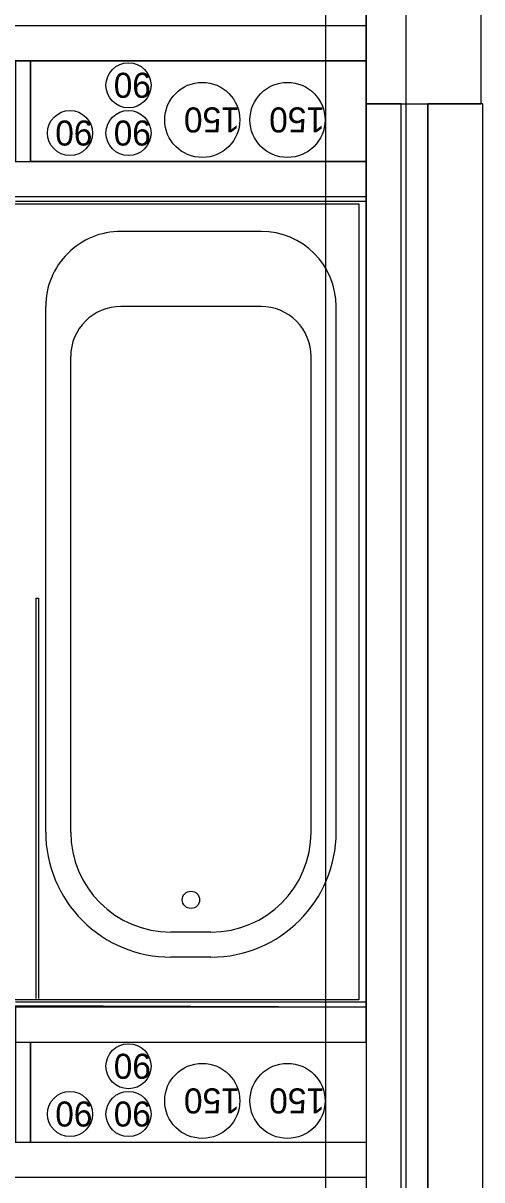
# Model space of a CAD drawing. Extents: x 1278 to 1356, y -253.7 to -224.
# Drawn here: x 1302.645 to 1303.561, y -239.071 to -236.76 of the extents above; entities that cross this region are included whole.
import ezdxf

# ---------------------------------------------------------------- set-up
doc = ezdxf.new("R2010")
doc.units = 0
for name, color, linetype in [('Level 1', 7, 'Continuous'), ('Level 11', 7, 'Continuous'), ('Level 36', 7, 'Continuous'), ('Level 41', 7, 'Continuous'), ('Level 65', 7, 'Continuous'), ('Level 66', 7, 'Continuous'), ('Level 67', 7, 'Continuous'), ('Level 70', 7, 'Continuous'), ('Level 93', 7, 'Continuous')]:
    doc.layers.add(name, color=color, linetype=linetype)

msp = doc.modelspace()

# ---------------------------------------------------------------- linework, layer by layer
at = {"layer": 'Level 1'}
for p, q in [((1301.8535, -236.8352), (1303.3298, -236.8352)), ((1303.3298, -238.7263), (1301.7835, -238.7263)), ((1303.3294, -239.0663), (1301.0027, -239.0663))]:
    msp.add_line(p, q, dxfattribs=at)
at = {"layer": 'Level 11'}
for p, q in [((1303.3298, -237.1163), (1302.6298, -237.1163)), ((1303.3298, -238.7163), (1303.3298, -237.1163)), ((1303.1198, -237.1763), (1302.8398, -237.1763)), ((1302.6898, -238.3763), (1302.6898, -237.3263)), ((1303.1198, -237.3263), (1302.8398, -237.3263)), ((1303.2698, -238.3763), (1303.2698, -237.3263)), ((1302.7398, -238.3763), (1302.7398, -237.4263)), ((1303.2198, -238.3763), (1303.2198, -237.4263)), ((1303.0198, -238.5763), (1302.9398, -238.5763)), ((1303.0198, -238.6263), (1302.9398, -238.6263)), ((1303.3298, -238.7163), (1302.6298, -238.7163))]:
    msp.add_line(p, q, dxfattribs=at)
msp.add_circle((1302.9798, -238.5118), 0.0173, dxfattribs=at)
for centre, radius, start, end in [((1302.8398, -237.3263), 0.15, 89.9999, 180.0002), ((1303.1198, -237.3263), 0.15, 360, 90), ((1302.8398, -237.4263), 0.1, 90.0001, 179.9999), ((1303.1198, -237.4263), 0.1, 360, 90.0001), ((1302.9398, -238.3763), 0.25, 180, 270.0001), ((1302.9398, -238.3763), 0.2, 180, 270), ((1303.0198, -238.3763), 0.25, 269.9999, 359.9999), ((1303.0198, -238.3763), 0.2, 270, 0)]:
    msp.add_arc(centre, radius, start, end, dxfattribs=at)
at = {"layer": 'Level 36'}
for p, q in [((1302.6702, -237.909), (1302.6702, -238.709)), ((1302.6702, -237.909), (1302.6752, -237.909)), ((1302.6702, -237.909), (1302.6702, -238.709)), ((1302.6702, -237.909), (1302.6752, -237.909)), ((1302.6702, -237.909), (1302.6702, -238.709)), ((1302.6702, -237.909), (1302.6752, -237.909)), ((1302.6752, -237.909), (1302.6752, -238.709)), ((1302.6752, -237.909), (1302.6752, -238.709)), ((1302.6752, -237.909), (1302.6752, -238.709))]:
    msp.add_line(p, q, dxfattribs=at)
at = {"layer": 'Level 41'}
for centre, radius in [((1302.8551, -236.8843), 0.045), ((1303.0024, -236.9535), 0.075), ((1303.1726, -236.9535), 0.075), ((1302.7383, -236.9797), 0.045), ((1302.8551, -236.9797), 0.045), ((1302.8551, -238.8443), 0.045), ((1303.0024, -238.9135), 0.075), ((1303.1726, -238.9135), 0.075), ((1302.7383, -238.9397), 0.045), ((1302.8551, -238.9397), 0.045)]:
    msp.add_circle(centre, radius, dxfattribs=at)
at = {"layer": 'Level 65'}
for p, q in [((1301.7685, -237.1213), (1303.3148, -237.1213)), ((1303.3148, -237.1213), (1303.3148, -238.7113)), ((1303.3148, -238.7113), (1301.7685, -238.7113))]:
    msp.add_line(p, q, dxfattribs=at)
at = {"layer": 'Level 66'}
for p, q in [((1303.3298, -237.0363), (1303.3298, -235.1452)), ((1301.0027, -236.7652), (1303.3294, -236.7652)), ((1301.9585, -236.7652), (1303.3294, -236.7652)), ((1302.6598, -236.8352), (1302.6598, -237.0363)), ((1303.3998, -242.8713), (1303.3998, -236.9213)), ((1303.4527, -242.8713), (1303.4527, -236.9213)), ((1301.8535, -237.0363), (1303.3298, -237.0363)), ((1301.7835, -237.1063), (1303.3298, -237.1063)), ((1303.3298, -238.7263), (1303.3298, -237.1063)), ((1302.6298, -238.7963), (1303.3298, -238.7963)), ((1302.6598, -238.7963), (1302.6598, -238.9963)), ((1303.3298, -238.7963), (1303.3298, -238.9963)), ((1301.8535, -238.9963), (1303.3298, -238.9963)), ((1303.3294, -239.0663), (1303.3294, -242.8713))]:
    msp.add_line(p, q, dxfattribs=at)
msp.add_lwpolyline([(1303.3294, -236.9213), (1303.5594, -236.9213), (1303.5594, -236.2213), (1303.3294, -236.2213)], close=True, dxfattribs=at)
msp.add_lwpolyline([(1303.3294, -236.9213), (1303.5594, -236.9213), (1303.5594, -236.2213), (1303.3294, -236.2213)], close=True, dxfattribs=at)
at = {"layer": 'Level 67'}
for points in [[(1303.3298, -236.8352), (1301.0727, -236.8352), (1301.0727, -237.1748), (1301.0027, -237.1748), (1301.0027, -236.7652), (1303.3298, -236.7652)], [(1301.7835, -236.8352), (1301.7835, -237.1063), (1303.3298, -237.1063), (1303.3298, -237.0363), (1302.6598, -237.0363), (1302.6598, -236.8352), (1302.6298, -236.8352), (1302.6298, -237.0363), (1301.8535, -237.0363), (1301.8535, -236.8352)], [(1303.3298, -242.8713), (1303.3998, -242.8713), (1303.3998, -236.9213), (1303.3298, -236.9213)], [(1303.4527, -242.8713), (1303.5627, -242.8713), (1303.5627, -236.9213), (1303.4527, -236.9213)], [(1303.3298, -238.9963), (1303.3298, -239.0663), (1301.0027, -239.0663), (1301.0027, -237.9048), (1301.0727, -237.9048), (1301.0727, -238.9963), (1301.7835, -238.9963), (1301.7835, -238.7263), (1302.6298, -238.7236), (1302.6298, -238.8486), (1301.8535, -238.8486), (1301.8535, -238.9963)], [(1303.3298, -238.7963), (1303.3298, -238.7263), (1302.6298, -238.7236), (1302.6298, -238.9963), (1302.6598, -238.9963), (1302.6598, -238.7963)]]:
    msp.add_lwpolyline(points, close=True, dxfattribs=at)
at = {"layer": 'Level 70'}
msp.add_line((1303.4094, -250.7923), (1303.4094, -229.6087), dxfattribs=at)
at = {"layer": 'Level 93'}
msp.add_line((1303.249, -246.757), (1303.249, -236.1407), dxfattribs=at)

# ---------------------------------------------------------------- texts
at = {"layer": 'Level 41'}
for s, p in [('90', (1302.9001, -236.8593)), ('150', (1303.0774, -236.9285)), ('150', (1303.2476, -236.9285)), ('90', (1302.7833, -236.9547)), ('90', (1302.9001, -236.9547)), ('90', (1302.9001, -238.8193)), ('150', (1303.0774, -238.8885)), ('150', (1303.2476, -238.8885)), ('90', (1302.7833, -238.9147)), ('90', (1302.9001, -238.9147))]:
    msp.add_text(s, height=0.05, rotation=180, dxfattribs=at).set_placement(p)

doc.saveas('drawing.dxf')
